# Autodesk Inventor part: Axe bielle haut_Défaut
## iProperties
Shininess: 64.0
Length Units: 11269
Angle Units: 11279
Time Units: 11290
Mass Units: 11283
Length Display Precision: 3
Angle Display Precision: 2
Compacted: True
Part Number: Axe bielle haut_Défaut
Document SubType Name: Modeling
Created: 2006-01
Material: Par défaut
Designer: riri
Density: 0.0
Volumn: 0.0
Area: 0.0
PropertySet Name: Model Information
Control State: 0
Master: False
Checked Out: False
Author: riri
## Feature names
1. Base1
